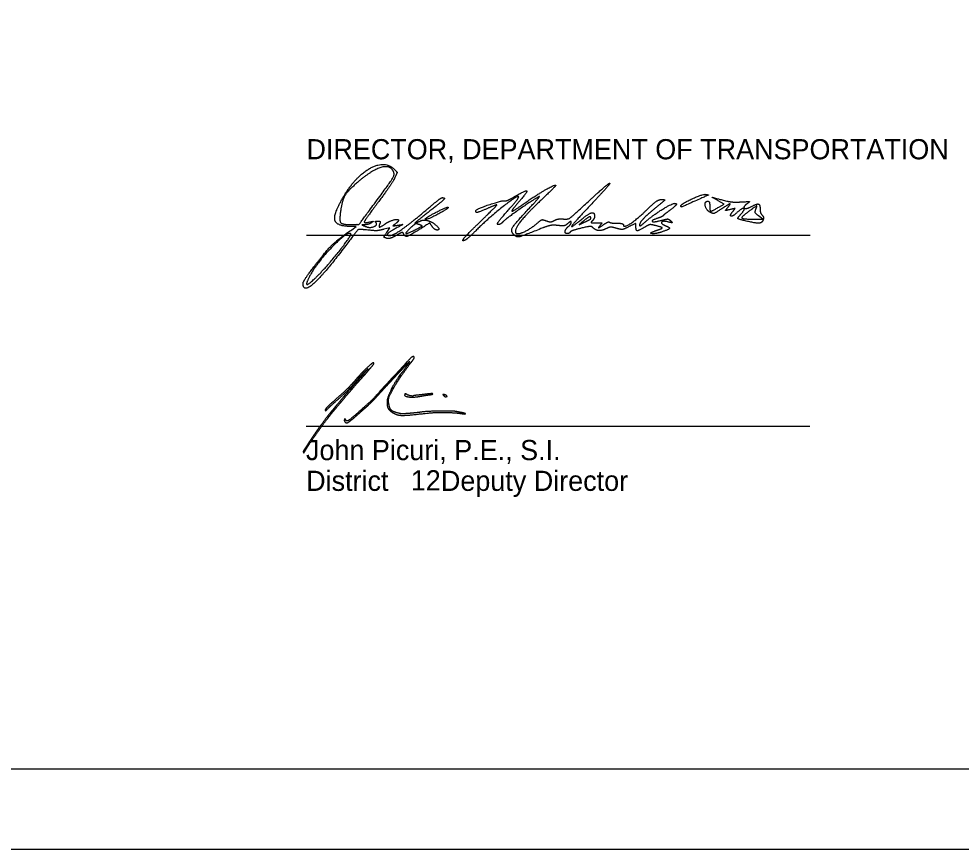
# Model space of a CAD drawing. Extents: x -0.3 to 41.5, y 0 to 22.
# Drawn here: x 24.85 to 30.74, y 0 to 5.19 of the extents above; entities that cross this region are included whole.
import ezdxf

# ---------------------------------------------------------------- set-up
doc = ezdxf.new("R2010")
doc.units = 0
for name, color, linetype in [('GM_X_Section', 7, 'Continuous'), ('SH_Border', 7, 'Continuous'), ('SH_Cut_Line', 7, 'Continuous'), ('SH_Data', 7, 'Continuous')]:
    doc.layers.add(name, color=color, linetype=linetype)

msp = doc.modelspace()

# ---------------------------------------------------------------- linework, layer by layer
at = {"layer": 'GM_X_Section'}
for p, q in [((27.0644, 4.0212), (27.0644, 4.0212)), ((28.9898, 4.0204), (28.9898, 4.0204)), ((27.3529, 3.9028), (27.3529, 3.9028)), ((27.3933, 3.9403), (27.3933, 3.9403)), ((27.7279, 3.9142), (27.7279, 3.9142)), ((28.4273, 3.9421), (28.4273, 3.9421)), ((29.3971, 3.9248), (29.3971, 3.9248)), ((26.7311, 3.5959), (26.7311, 3.5959)), ((26.6273, 3.5357), (26.6273, 3.5357)), ((27.2746, 2.8288), (27.2746, 2.8288)), ((27.5082, 2.833), (27.5082, 2.833)), ((26.8938, 2.6658), (26.8938, 2.6658)), ((26.6282, 2.4815), (26.6282, 2.4815))]:
    msp.add_line(p, q, dxfattribs=at)
for points in [[(29.2272, 4.0118), (29.26, 4.0312), (29.2233, 4.0518)], [(29.4511, 3.9366), (29.5017, 3.9367), (29.4758, 3.9566)], [(26.9316, 3.8709), (26.9592, 3.89), (26.9251, 3.8906)], [(28.3808, 3.9244), (28.3542, 3.9013), (28.3908, 3.9191)], [(27.1502, 3.853), (27.1693, 3.8822), (27.1317, 3.8731)]]:
    msp.add_lwpolyline(points, dxfattribs=at)
for points in [[(26.8743, 4.0669), (26.9519, 4.2022), (27.1392, 4.3066), (27.1983, 4.2475)], [(27.1902, 4.2393), (27.1669, 4.2771), (27.0534, 4.24), (26.9676, 4.1666)], [(27.1983, 4.2475), (27.2152, 4.2306), (27.2152, 4.2261), (27.1988, 4.1915)], [(27.0644, 4.0212), (27.1737, 4.1683), (27.2029, 4.2189), (27.1902, 4.2393)], [(27.1988, 4.1915), (27.1889, 4.1708), (27.1423, 4.1028), (27.0953, 4.0404)], [(26.9676, 4.1666), (26.9076, 4.1152), (26.8726, 4.0575), (26.8627, 3.9934)], [(28.0026, 4.0295), (28.0751, 4.0804), (28.1933, 4.1499), (28.2074, 4.1499)], [(28.2074, 4.1499), (28.2118, 4.1499), (28.1747, 4.1116), (28.1248, 4.0647)], [(28.4115, 4.0479), (28.479, 4.11), (28.5384, 4.161), (28.5436, 4.1611)], [(28.5436, 4.1611), (28.5487, 4.1611), (28.5019, 4.107), (28.4395, 4.0408)], [(26.9251, 3.8906), (26.837, 3.8921), (26.8159, 3.9651), (26.8743, 4.0669)], [(27.4054, 4.0007), (27.4508, 4.0393), (27.4917, 4.0709), (27.4964, 4.071)], [(27.4964, 4.071), (27.5188, 4.0715), (27.4977, 4.0485), (27.4204, 3.9879)], [(27.9748, 4.0774), (27.9662, 4.0861), (27.7774, 3.9358), (27.7073, 3.8645)], [(28.1011, 4.077), (28.0569, 4.052), (27.8874, 3.933), (27.8755, 3.9187)], [(27.8905, 4.0513), (27.8955, 4.0497), (27.9221, 4.0615), (27.9496, 4.0776)], [(27.9048, 3.9871), (27.9465, 4.0336), (27.978, 4.0743), (27.9748, 4.0774)], [(27.9496, 4.0776), (28.0205, 4.1192), (28.0315, 4.1073), (27.9782, 4.0467)], [(28.0424, 4.006), (28.084, 4.0503), (28.1103, 4.0823), (28.1011, 4.077)], [(28.9898, 4.0204), (28.9898, 4.0316), (29.1274, 4.0949), (29.1444, 4.0915)], [(29.1444, 4.0915), (29.163, 4.0879), (29.1637, 4.0883), (29.0542, 4.0391)], [(29.2233, 4.0518), (29.1848, 4.0735), (29.1839, 4.0735), (29.2767, 4.0498)], [(26.9329, 3.9024), (26.9749, 3.9024), (26.979, 3.9061), (27.0644, 4.0212)], [(27.0953, 4.0404), (27.0483, 3.978), (27.0098, 3.9234), (27.0098, 3.9191)], [(27.3933, 3.9403), (27.4116, 3.9564), (27.5304, 4.0156), (27.5351, 4.0109)], [(27.5351, 4.0109), (27.5406, 4.0054), (27.4123, 3.9362), (27.3964, 3.9362)], [(27.7075, 3.9896), (27.7077, 3.9991), (27.8763, 4.056), (27.8905, 4.0513)], [(27.7279, 3.9142), (27.7918, 3.9758), (27.8416, 4.0262), (27.8385, 4.0262)], [(27.8385, 4.0262), (27.8354, 4.0262), (27.8093, 4.0161), (27.7804, 4.0037)], [(27.9782, 4.0467), (27.9529, 4.0181), (27.9323, 3.9913), (27.9323, 3.9873)], [(27.9323, 3.9873), (27.9323, 3.9833), (27.964, 4.0023), (28.0026, 4.0295)], [(28.1248, 4.0647), (28.0352, 3.9804), (27.9548, 3.883), (27.9548, 3.8588)], [(28.254, 3.9377), (28.2841, 3.9352), (28.3052, 3.95), (28.4115, 4.0479)], [(28.4395, 4.0408), (28.3229, 3.917), (28.2941, 3.8744), (28.368, 3.9354)], [(28.8436, 4.0173), (28.7769, 3.9624), (28.7311, 3.9142), (28.7311, 3.8992)], [(28.762, 3.9152), (28.8103, 3.9591), (28.9425, 4.0401), (28.9577, 4.035)], [(28.7789, 3.9972), (28.8196, 4.0366), (28.853, 4.0598), (28.8689, 4.0594)], [(28.8689, 4.0594), (28.8908, 4.059), (28.8873, 4.0533), (28.8436, 4.0173)], [(28.9577, 4.035), (28.9653, 4.0325), (28.9516, 4.0157), (28.9272, 3.9975)], [(29.0542, 4.0391), (28.9979, 4.0138), (28.9898, 4.0115), (28.9898, 4.0204)], [(29.1707, 3.9807), (29.1469, 3.9935), (29.137, 4.0487), (29.1586, 4.0487)], [(29.1586, 4.0487), (29.1648, 4.0487), (29.1698, 4.036), (29.1698, 4.0206)], [(29.1698, 4.0206), (29.1698, 3.9874), (29.1827, 3.9855), (29.2272, 4.0118)], [(29.2809, 4.0075), (29.3028, 4.0341), (29.2886, 4.0307), (29.238, 3.9972)], [(29.2983, 3.9969), (29.2686, 3.9895), (29.2669, 3.9905), (29.2809, 4.0075)], [(29.2767, 4.0498), (29.2953, 4.045), (29.3358, 4.0426), (29.3667, 4.0443)], [(29.3667, 4.0443), (29.4161, 4.0471), (29.4205, 4.0456), (29.4026, 4.0323)], [(29.4026, 4.0323), (29.3766, 4.0129), (29.3973, 3.9982), (29.4276, 4.0144)], [(29.4581, 3.9976), (29.467, 4.0208), (29.4596, 4.018), (29.4032, 3.977)], [(29.4276, 4.0144), (29.4638, 4.0338), (29.4848, 4.0286), (29.4848, 4.0003)], [(26.8627, 3.9934), (26.8524, 3.9274), (26.8717, 3.9024), (26.9329, 3.9024)], [(27.1702, 3.8349), (27.1909, 3.8349), (27.3044, 3.9149), (27.4054, 4.0007)], [(27.4204, 3.9879), (27.3365, 3.9222), (27.3172, 3.9028), (27.3567, 3.924)], [(27.7804, 4.0037), (27.7241, 3.9795), (27.7072, 3.9763), (27.7075, 3.9896)], [(27.8456, 3.9024), (27.8363, 3.9024), (27.8623, 3.9396), (27.9048, 3.9871)], [(27.946, 3.8389), (27.9233, 3.8616), (27.9494, 3.9067), (28.0424, 4.006)], [(28.368, 3.9354), (28.4116, 3.9713), (28.4498, 3.9806), (28.4498, 3.9553)], [(28.4273, 3.9421), (28.4273, 3.9542), (28.4056, 3.946), (28.3808, 3.9244)], [(28.4498, 3.9553), (28.4498, 3.9473), (28.4437, 3.9346), (28.4363, 3.9272)], [(28.6298, 3.9011), (28.6298, 3.8805), (28.7156, 3.9358), (28.7789, 3.9972)], [(28.8773, 3.9575), (28.8742, 3.9536), (28.8603, 3.9469), (28.8464, 3.9426)], [(28.9272, 3.9975), (28.9028, 3.9793), (28.8804, 3.9613), (28.8773, 3.9575)], [(29.238, 3.9972), (29.2019, 3.9733), (29.19, 3.9704), (29.1707, 3.9807)], [(29.3164, 3.9873), (29.3296, 4.0031), (29.3275, 4.0042), (29.2983, 3.9969)], [(29.3423, 3.9794), (29.3135, 3.9524), (29.2928, 3.9587), (29.3164, 3.9873)], [(29.3649, 3.968), (29.3924, 3.9983), (29.3729, 4.0081), (29.3423, 3.9794)], [(29.3971, 3.9248), (29.3478, 3.9365), (29.3427, 3.9434), (29.3649, 3.968)], [(29.4032, 3.977), (29.3648, 3.949), (29.3796, 3.9365), (29.4511, 3.9366)], [(29.4758, 3.9566), (29.4575, 3.9707), (29.4523, 3.9826), (29.4581, 3.9976)], [(29.4848, 4.0003), (29.4848, 3.9861), (29.4906, 3.9687), (29.4976, 3.9617)], [(29.4976, 3.9617), (29.5046, 3.9547), (29.5073, 3.941), (29.5035, 3.9313)], [(27.0154, 3.9019), (26.9953, 3.9011), (26.9957, 3.8999), (27.0192, 3.8905)], [(27.0098, 3.9191), (27.0098, 3.9148), (27.0237, 3.9145), (27.0408, 3.9184)], [(27.0548, 3.9142), (27.0455, 3.9079), (27.0278, 3.9024), (27.0154, 3.9019)], [(27.0192, 3.8905), (27.0461, 3.8797), (27.0967, 3.9018), (27.081, 3.9175)], [(27.0408, 3.9184), (27.0637, 3.9238), (27.0673, 3.9227), (27.0548, 3.9142)], [(27.081, 3.9175), (27.0769, 3.9216), (27.0825, 3.9249), (27.0935, 3.9249)], [(27.0935, 3.9249), (27.1066, 3.9249), (27.1113, 3.9192), (27.107, 3.9081)], [(27.107, 3.9081), (27.099, 3.8871), (27.1105, 3.8865), (27.1395, 3.9064)], [(27.1395, 3.9064), (27.1655, 3.9242), (27.2236, 3.94), (27.2236, 3.9292)], [(27.2041, 3.9076), (27.1871, 3.8951), (27.1889, 3.894), (27.2182, 3.8984)], [(27.2236, 3.9292), (27.2236, 3.9251), (27.2148, 3.9154), (27.2041, 3.9076)], [(27.2182, 3.8984), (27.2513, 3.9034), (27.2512, 3.9032), (27.2102, 3.8806)], [(27.3529, 3.9028), (27.3374, 3.9085), (27.3226, 3.9039), (27.3051, 3.8879)], [(27.3276, 3.8701), (27.3694, 3.8914), (27.3726, 3.8956), (27.3529, 3.9028)], [(27.3567, 3.924), (27.3681, 3.9301), (27.3896, 3.9319), (27.4046, 3.9282)], [(27.4343, 3.8909), (27.4191, 3.9126), (27.4173, 3.9122), (27.3581, 3.874)], [(27.3964, 3.9362), (27.3921, 3.9362), (27.3907, 3.938), (27.3933, 3.9403)], [(27.4046, 3.9282), (27.437, 3.9199), (27.4896, 3.8687), (27.4655, 3.8687)], [(27.4655, 3.8687), (27.4569, 3.8687), (27.4428, 3.8787), (27.4343, 3.8909)], [(27.6286, 3.8018), (27.6193, 3.802), (27.664, 3.8526), (27.7279, 3.9142)], [(27.8755, 3.9187), (27.8681, 3.9097), (27.8546, 3.9024), (27.8456, 3.9024)], [(27.9711, 3.8462), (27.9906, 3.8462), (28.0638, 3.8869), (28.0966, 3.916)], [(28.0966, 3.916), (28.1148, 3.9322), (28.1264, 3.9346), (28.1478, 3.9264)], [(28.2207, 3.8971), (28.1944, 3.9004), (28.1585, 3.8946), (28.1257, 3.8817)], [(28.1478, 3.9264), (28.1659, 3.9195), (28.1829, 3.9202), (28.1973, 3.9283)], [(28.1973, 3.9283), (28.2093, 3.9351), (28.2348, 3.9393), (28.254, 3.9377)], [(28.2833, 3.9101), (28.2692, 3.8973), (28.25, 3.8933), (28.2207, 3.8971)], [(28.2804, 3.8462), (28.2639, 3.8462), (28.268, 3.8757), (28.2867, 3.8912)], [(28.3036, 3.9168), (28.3036, 3.9232), (28.2944, 3.9202), (28.2833, 3.9101)], [(28.2867, 3.8912), (28.296, 3.8989), (28.3036, 3.9104), (28.3036, 3.9168)], [(28.4412, 3.8818), (28.4312, 3.8918), (28.4131, 3.8914), (28.3653, 3.8799)], [(28.3908, 3.9191), (28.4109, 3.9288), (28.4273, 3.9392), (28.4273, 3.9421)], [(28.4363, 3.9272), (28.4258, 3.9167), (28.4311, 3.9137), (28.4602, 3.9137)], [(28.4602, 3.9137), (28.494, 3.9137), (28.4961, 3.9118), (28.4821, 3.8944)], [(28.4821, 3.8944), (28.4713, 3.881), (28.4772, 3.8825), (28.5017, 3.8997)], [(28.5017, 3.8997), (28.521, 3.9132), (28.5396, 3.9214), (28.5432, 3.9179)], [(28.5432, 3.9179), (28.5467, 3.9143), (28.5676, 3.9114), (28.5897, 3.9114)], [(28.6661, 3.8899), (28.6324, 3.8732), (28.6157, 3.8711), (28.5859, 3.8796)], [(28.5897, 3.9114), (28.6118, 3.9114), (28.6298, 3.9068), (28.6298, 3.9011)], [(28.7086, 3.8898), (28.7086, 3.9104), (28.7076, 3.9104), (28.6661, 3.8899)], [(28.7643, 3.8871), (28.7238, 3.8631), (28.7086, 3.8639), (28.7086, 3.8898)], [(28.7311, 3.8992), (28.7311, 3.8925), (28.745, 3.8997), (28.762, 3.9152)], [(28.8392, 3.8943), (28.8042, 3.9032), (28.7891, 3.9017), (28.7643, 3.8871)], [(28.8464, 3.9426), (28.8018, 3.9287), (28.8193, 3.9164), (28.866, 3.9288)], [(28.8661, 3.877), (28.8763, 3.8807), (28.8658, 3.8875), (28.8392, 3.8943)], [(28.866, 3.9288), (28.9005, 3.938), (28.9142, 3.9375), (28.9251, 3.9265)], [(28.9083, 3.9197), (28.8752, 3.9279), (28.8633, 3.9071), (28.8942, 3.8953)], [(28.8942, 3.8953), (28.9217, 3.8847), (28.9137, 3.8713), (28.8716, 3.8574)], [(28.9251, 3.9265), (28.9365, 3.9149), (28.9333, 3.9136), (28.9083, 3.9197)], [(29.5035, 3.9313), (29.4963, 3.9124), (29.4592, 3.9101), (29.3971, 3.9248)], [(26.9252, 3.8446), (26.9063, 3.8634), (26.7097, 3.6603), (26.668, 3.579)], [(26.7057, 3.653), (26.7756, 3.7434), (26.8477, 3.8129), (26.9316, 3.8709)], [(26.7311, 3.5959), (26.7919, 3.658), (26.9321, 3.8377), (26.9252, 3.8446)], [(27.0047, 3.871), (26.9746, 3.874), (26.964, 3.8646), (26.895, 3.7731)], [(27.1317, 3.8731), (27.0954, 3.8643), (27.0753, 3.864), (27.0047, 3.871)], [(27.1491, 3.817), (27.1328, 3.8233), (27.1329, 3.8266), (27.1502, 3.853)], [(27.2091, 3.8349), (27.186, 3.8212), (27.159, 3.8132), (27.1491, 3.817)], [(27.2102, 3.8806), (27.1643, 3.8552), (27.1465, 3.8349), (27.1702, 3.8349)], [(27.2551, 3.8473), (27.2525, 3.855), (27.2352, 3.8503), (27.2091, 3.8349)], [(27.3581, 3.874), (27.2961, 3.8341), (27.2624, 3.8253), (27.2551, 3.8473)], [(27.3051, 3.8879), (27.2653, 3.8515), (27.2754, 3.8435), (27.3276, 3.8701)], [(27.7073, 3.8645), (27.6733, 3.8299), (27.6378, 3.8017), (27.6286, 3.8018)], [(28.1257, 3.8817), (27.9942, 3.8297), (27.9627, 3.8222), (27.946, 3.8389)], [(27.9548, 3.8588), (27.9548, 3.8518), (27.9621, 3.8462), (27.9711, 3.8462)], [(28.2968, 3.8555), (28.2936, 3.8504), (28.2862, 3.8462), (28.2804, 3.8462)], [(28.3653, 3.8799), (28.3308, 3.8716), (28.2999, 3.8607), (28.2968, 3.8555)], [(28.5279, 3.8796), (28.5002, 3.8648), (28.4571, 3.8659), (28.4412, 3.8818)], [(28.5859, 3.8796), (28.5617, 3.8866), (28.5409, 3.8866), (28.5279, 3.8796)], [(28.8716, 3.8574), (28.8297, 3.8436), (28.7871, 3.8487), (28.8267, 3.8628)], [(28.8267, 3.8628), (28.8391, 3.8672), (28.8568, 3.8736), (28.8661, 3.877)], [(26.895, 3.7731), (26.7579, 3.5912), (26.6273, 3.4754), (26.6273, 3.5357)], [(26.6273, 3.5357), (26.6273, 3.5444), (26.6626, 3.5971), (26.7057, 3.653)], [(26.668, 3.579), (26.6399, 3.5241), (26.6683, 3.5318), (26.7311, 3.5959)], [(27.3194, 3.0774), (27.315, 3.0818), (27.2853, 3.0546), (27.246, 3.01)], [(27.3141, 3.0563), (27.3205, 3.0646), (27.3229, 3.0739), (27.3194, 3.0774)], [(27.0672, 3.0394), (27.0648, 3.0409), (27.0433, 3.0236), (27.019, 3.0007)], [(27.037, 2.9926), (27.0425, 2.9995), (27.05, 3.0084), (27.0537, 3.0124)], [(27.0537, 3.0124), (27.0672, 3.027), (27.0719, 3.0365), (27.0672, 3.0394)], [(27.246, 3.01), (27.2392, 3.0022), (27.2207, 2.9824), (27.2049, 2.966)], [(27.2142, 2.9162), (27.2251, 2.9343), (27.2919, 3.028), (27.3141, 3.0563)], [(27.2934, 3.0474), (27.2982, 3.0504), (27.2483, 2.9798), (27.2415, 2.974)], [(27.2479, 3), (27.2648, 3.019), (27.2901, 3.0454), (27.2934, 3.0474)], [(26.8587, 2.7863), (26.9096, 2.8474), (26.9284, 2.8691), (27.0101, 2.961)], [(26.9846, 2.9457), (26.9825, 2.9437), (26.8912, 2.8394), (26.8882, 2.8357)], [(27.019, 3.0007), (27.0056, 2.9881), (26.9697, 2.9494), (26.9512, 2.9277)], [(26.97, 2.9367), (26.9834, 2.9523), (27.0041, 2.9743), (27.0158, 2.9856)], [(27.0307, 2.9984), (27.0228, 2.9891), (26.9864, 2.9475), (26.9846, 2.9457)], [(27.0101, 2.961), (27.0194, 2.9715), (27.0315, 2.9857), (27.037, 2.9926)], [(27.0158, 2.9856), (27.0276, 2.9969), (27.0343, 3.0027), (27.0307, 2.9984)], [(27.2049, 2.966), (27.1891, 2.9495), (27.1729, 2.9322), (27.1689, 2.9274)], [(27.2415, 2.974), (27.2356, 2.969), (27.1775, 2.8763), (27.1775, 2.8719)], [(27.1943, 2.9432), (27.2026, 2.9524), (27.2158, 2.9664), (27.2237, 2.9743)], [(27.2237, 2.9743), (27.2315, 2.9822), (27.2424, 2.9938), (27.2479, 3)], [(26.8291, 2.7961), (26.8776, 2.8383), (26.9306, 2.8911), (26.97, 2.9367)], [(26.9512, 2.9277), (26.9283, 2.9009), (26.8778, 2.851), (26.8432, 2.8212)], [(27.1443, 2.9007), (27.1348, 2.8908), (27.1167, 2.8712), (27.1041, 2.857)], [(27.1129, 2.8554), (27.1162, 2.8591), (27.1325, 2.8766), (27.149, 2.8943)], [(27.1689, 2.9274), (27.1649, 2.9226), (27.1538, 2.9106), (27.1443, 2.9007)], [(27.149, 2.8943), (27.1656, 2.912), (27.1859, 2.934), (27.1943, 2.9432)], [(27.1669, 2.7668), (27.1576, 2.8015), (27.1713, 2.845), (27.2142, 2.9162)], [(26.883, 2.8293), (26.8815, 2.8276), (26.8649, 2.8076), (26.8461, 2.785)], [(26.8882, 2.8357), (26.8868, 2.8339), (26.8844, 2.831), (26.883, 2.8293)], [(27.1041, 2.857), (27.0665, 2.8148), (27.0519, 2.8), (27.0166, 2.7686)], [(27.0254, 2.7653), (27.0396, 2.7777), (27.0715, 2.8096), (27.0888, 2.8287)], [(27.0888, 2.8287), (27.0987, 2.8397), (27.1095, 2.8517), (27.1129, 2.8554)], [(27.1728, 2.8598), (27.1568, 2.824), (27.1502, 2.7901), (27.1544, 2.7663)], [(27.1775, 2.8719), (27.1775, 2.871), (27.1754, 2.8655), (27.1728, 2.8598)], [(27.2752, 2.8416), (27.2698, 2.8464), (27.2623, 2.8441), (27.2623, 2.8375)], [(27.2623, 2.8375), (27.2623, 2.8341), (27.2658, 2.8316), (27.2746, 2.8288)], [(27.2746, 2.8288), (27.2894, 2.824), (27.3386, 2.8252), (27.3665, 2.831)], [(27.3169, 2.8326), (27.3157, 2.8295), (27.28, 2.8372), (27.2752, 2.8416)], [(27.3356, 2.8361), (27.3257, 2.8352), (27.3173, 2.8336), (27.3169, 2.8326)], [(27.3755, 2.8405), (27.3635, 2.839), (27.3455, 2.837), (27.3356, 2.8361)], [(27.3665, 2.831), (27.3764, 2.8331), (27.3955, 2.8362), (27.4089, 2.838)], [(27.437, 2.8463), (27.4358, 2.8473), (27.4083, 2.8447), (27.3755, 2.8405)], [(27.4089, 2.838), (27.4308, 2.8408), (27.4403, 2.8436), (27.437, 2.8463)], [(27.5018, 2.8415), (27.5012, 2.8409), (27.5041, 2.8371), (27.5082, 2.833)], [(27.5252, 2.8331), (27.5217, 2.8365), (27.5035, 2.8432), (27.5018, 2.8415)], [(27.5082, 2.833), (27.513, 2.8282), (27.5174, 2.826), (27.5208, 2.8269)], [(27.5208, 2.8269), (27.5278, 2.8286), (27.5286, 2.8296), (27.5252, 2.8331)], [(26.8432, 2.8212), (26.8031, 2.7866), (26.7661, 2.7506), (26.7661, 2.7462)], [(26.7868, 2.757), (26.7959, 2.7663), (26.8149, 2.7839), (26.8291, 2.7961)], [(26.8461, 2.785), (26.8273, 2.7624), (26.8071, 2.7382), (26.8012, 2.7312)], [(26.8176, 2.7374), (26.8184, 2.7382), (26.8368, 2.7601), (26.8587, 2.7863)], [(26.8012, 2.7312), (26.7903, 2.7183), (26.757, 2.6743), (26.7222, 2.6265)], [(26.7661, 2.7462), (26.7661, 2.7385), (26.7713, 2.7412), (26.7868, 2.757)], [(26.7747, 2.6834), (26.7912, 2.7048), (26.8158, 2.7358), (26.8176, 2.7374)], [(27.0166, 2.7686), (26.9422, 2.7026), (26.9087, 2.6757), (26.9006, 2.6757)], [(26.9538, 2.7024), (26.9601, 2.7082), (26.9773, 2.7234), (26.992, 2.7362)], [(26.992, 2.7362), (27.0066, 2.7489), (27.0216, 2.762), (27.0254, 2.7653)], [(27.1544, 2.7663), (27.1562, 2.7563), (27.1732, 2.7365), (27.1873, 2.7281)], [(27.2276, 2.7234), (27.1953, 2.7309), (27.1721, 2.7474), (27.1669, 2.7668)], [(27.1873, 2.7281), (27.2114, 2.7136), (27.2564, 2.7087), (27.3112, 2.7145)], [(27.2942, 2.7233), (27.2496, 2.7197), (27.2435, 2.7197), (27.2276, 2.7234)], [(27.3498, 2.7285), (27.3462, 2.7279), (27.3212, 2.7255), (27.2942, 2.7233)], [(27.3112, 2.7145), (27.4286, 2.727), (27.4599, 2.729), (27.5222, 2.7281)], [(27.5002, 2.7374), (27.4518, 2.7374), (27.3711, 2.7326), (27.3498, 2.7285)], [(27.6191, 2.728), (27.5857, 2.7352), (27.5577, 2.7375), (27.5002, 2.7374)], [(27.5222, 2.7281), (27.5675, 2.7275), (27.5852, 2.7262), (27.6256, 2.7205)], [(27.6256, 2.7205), (27.6451, 2.7177), (27.6402, 2.7235), (27.6191, 2.728)], [(26.6399, 2.4883), (26.6568, 2.5183), (26.7373, 2.6348), (26.7747, 2.6834)], [(26.886, 2.6847), (26.8839, 2.6794), (26.8882, 2.669), (26.8938, 2.6658)], [(26.8942, 2.6822), (26.8908, 2.6895), (26.8881, 2.6903), (26.886, 2.6847)], [(26.8938, 2.6658), (26.8964, 2.6643), (26.9008, 2.6638), (26.9035, 2.6646)], [(26.9006, 2.6757), (26.8987, 2.6757), (26.8958, 2.6786), (26.8942, 2.6822)], [(26.9035, 2.6646), (26.9096, 2.6664), (26.9377, 2.6876), (26.9538, 2.7024)], [(26.7222, 2.6265), (26.7115, 2.6119), (26.6902, 2.5808), (26.675, 2.5574)], [(26.675, 2.5574), (26.6597, 2.5341), (26.6426, 2.5083), (26.637, 2.5001)], [(26.637, 2.5001), (26.6313, 2.4919), (26.6274, 2.4836), (26.6282, 2.4815)], [(26.6282, 2.4815), (26.6305, 2.4753), (26.6336, 2.4771), (26.6399, 2.4883)]]:
    msp.add_open_spline(points, degree=2, dxfattribs=at)
at = {"layer": 'SH_Border'}
msp.add_lwpolyline([(0, 0), (34, 0), (34, 22), (0, 22)], close=True, dxfattribs=at)
at = {"layer": 'SH_Cut_Line'}
for p, q in [((26.6484, 3.8366), (29.7984, 3.8366)), ((26.6466, 2.6436), (29.7966, 2.6436))]:
    msp.add_line(p, q, dxfattribs=at)
at = {"layer": 'SH_Data'}
msp.add_lwpolyline([(1.5, 21.5), (33.5, 21.5), (33.5, 0.5), (1.5, 0.5)], close=True, dxfattribs=at)

# ---------------------------------------------------------------- texts
at = {"layer": 'GM_X_Section'}
for s, p in [('DIRECTOR, DEPARTMENT OF TRANSPORTATION', (26.6484, 4.3108)), ('John Picuri, P.E., S.I.', (26.6454, 2.4308)), ('District       Deputy Director', (26.6466, 2.2386)), ('              12', (26.6454, 2.2418))]:
    msp.add_text(s, height=0.126, dxfattribs=at).set_placement(p)

doc.saveas('drawing.dxf')
